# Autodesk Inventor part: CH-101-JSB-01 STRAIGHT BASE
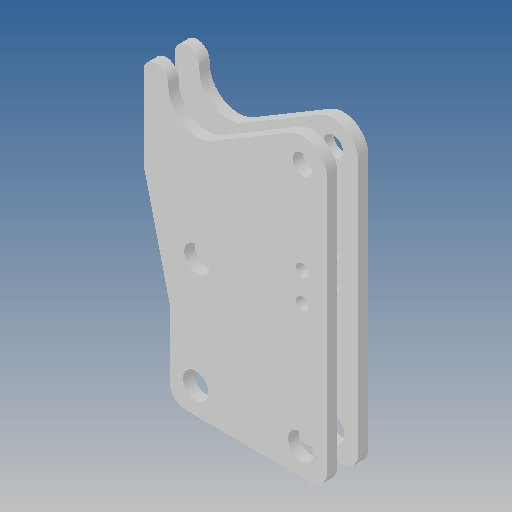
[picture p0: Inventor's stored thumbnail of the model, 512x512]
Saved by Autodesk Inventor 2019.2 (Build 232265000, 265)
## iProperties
Created: 2012-09
Part Number: CH-101-JSB-01 STRAIGHT BASE
Material: Ogólny
Document SubType Name: Modeling
Designer: CADENGINEERING4
Density: 1 g/cm^3
Appearance: Domyślna
Author: CADENGINEERING4
Revision Number: ÈÎºÎ
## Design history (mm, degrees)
feature "À­Éì3"
feature "¾µÏò3"
node "Bryła1"
node "Bryła2"
